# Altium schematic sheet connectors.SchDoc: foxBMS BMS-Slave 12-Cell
size A3; DocumentNumber: 10; SheetNumber: 10; SheetTotal: 15; AUTHOR: Fraunhofer IISB foxBMS Team; SheetDescription: Connectors
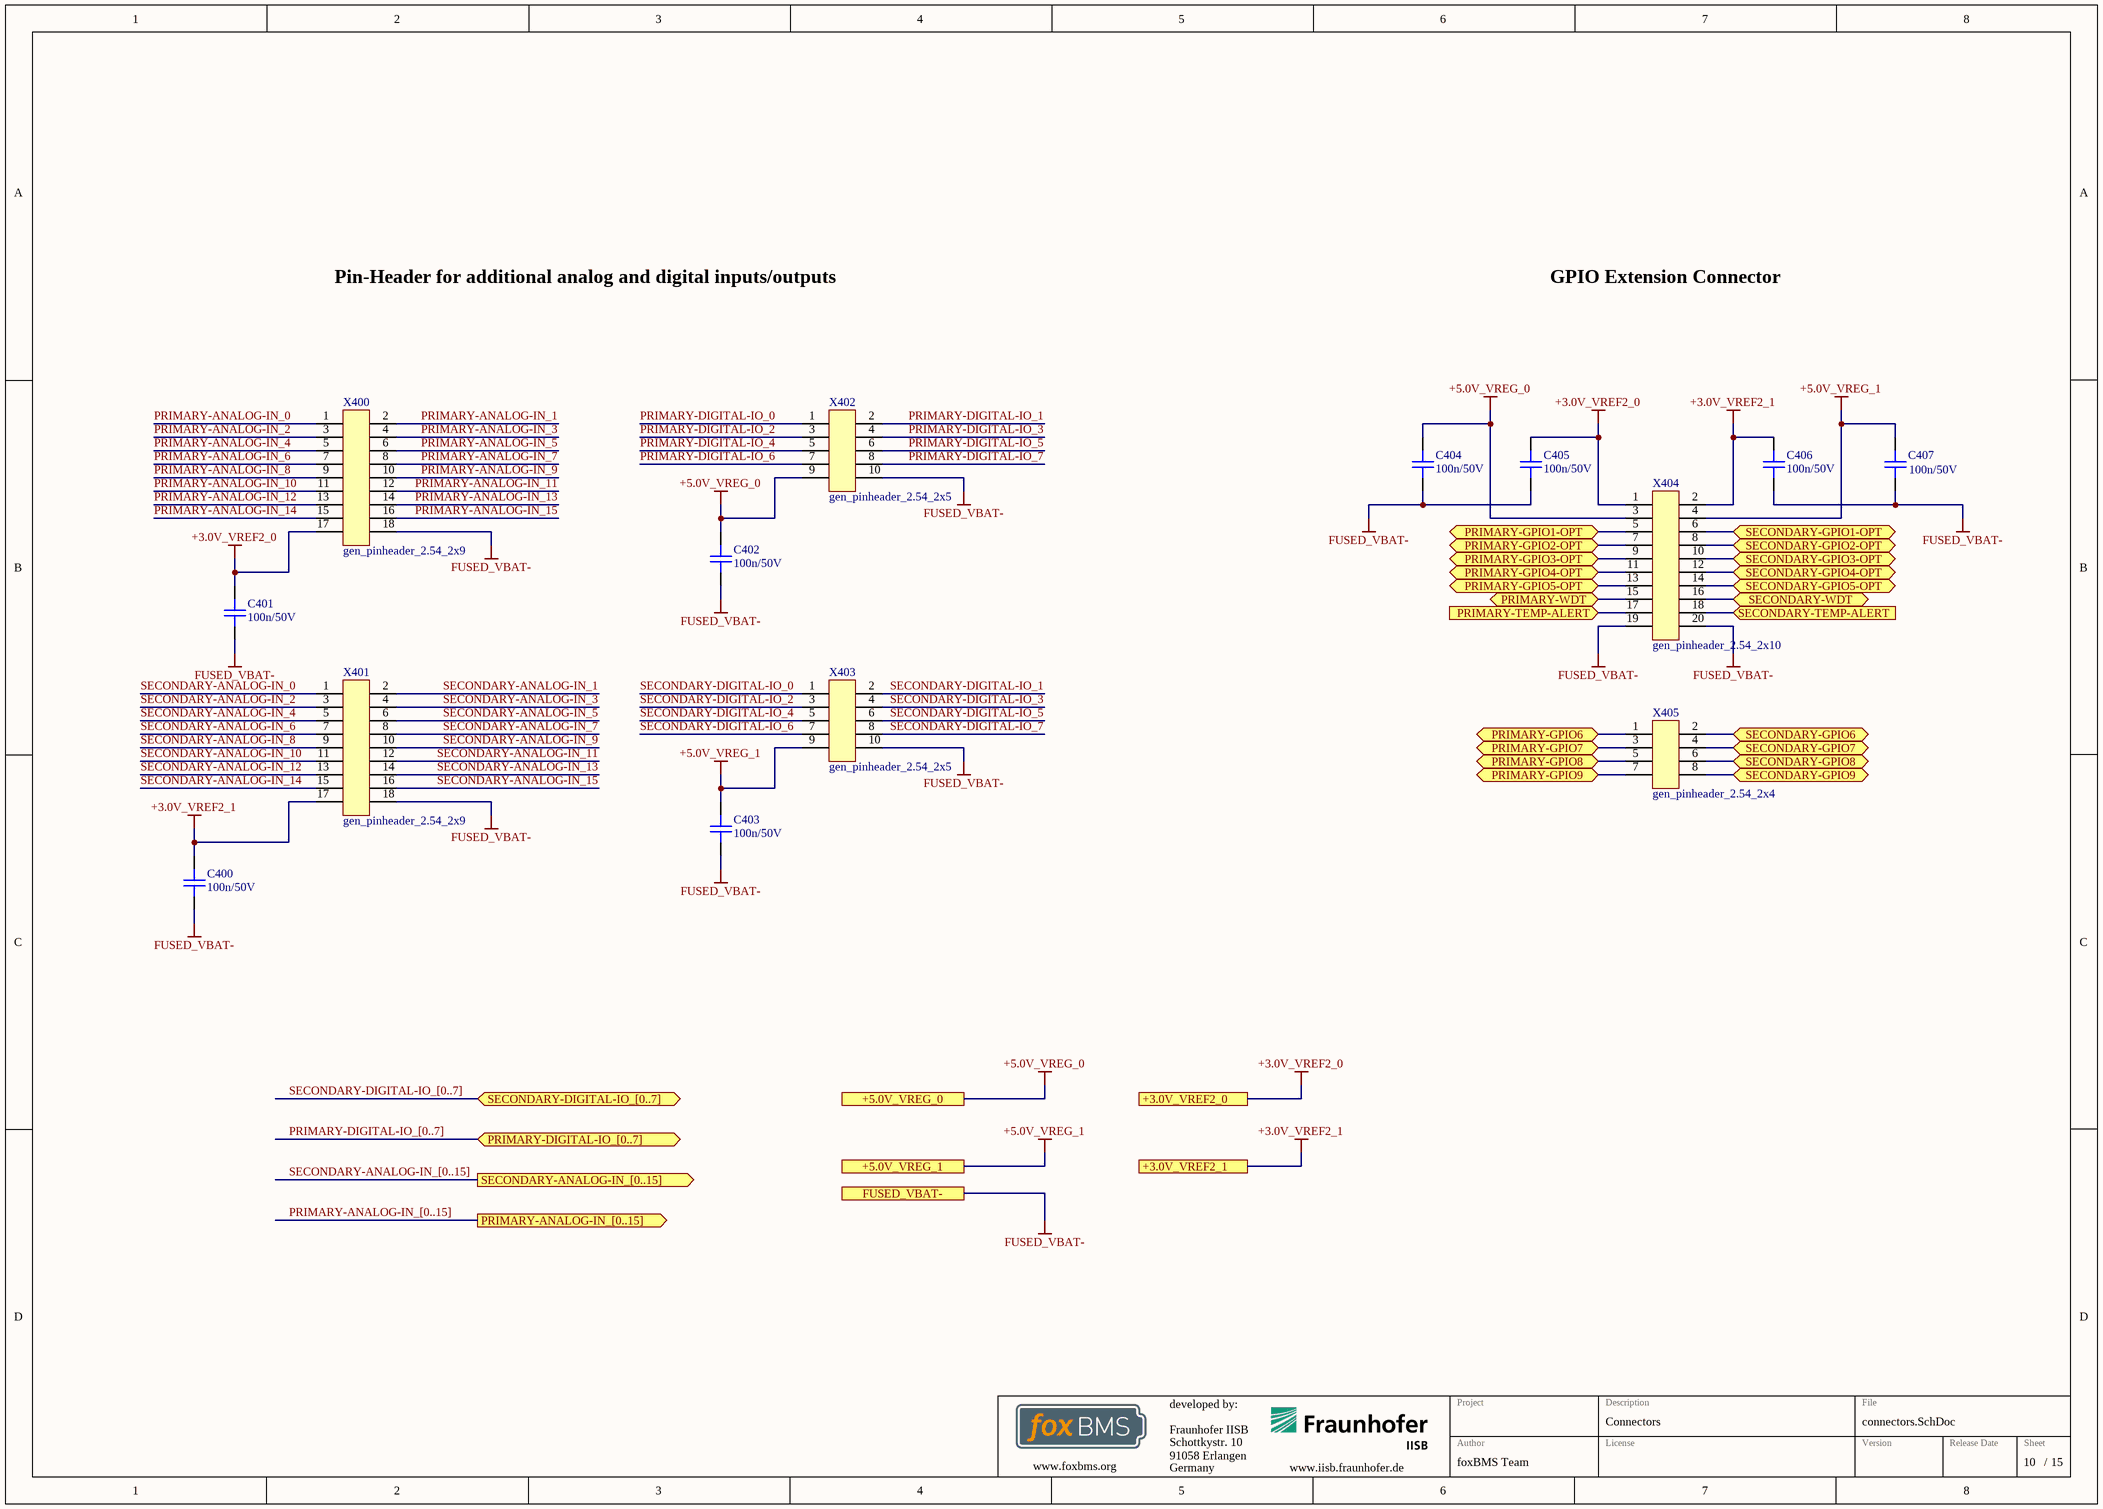
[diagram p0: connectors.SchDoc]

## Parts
C400  100n/50V  [CAPC1608X08N]
C401  100n/50V  [CAPC1608X08N]
C402  100n/50V  [CAPC1608X08N]
C403  100n/50V  [CAPC1608X08N]
C404  100n/50V  [CAPC1608X08N]
C405  100n/50V  [CAPC1608X08N]
C406  100n/50V  [CAPC1608X08N]
C407  100n/50V  [CAPC1608X08N]
X400  gen_pinheader_2.54_2x9  [Pinheader_2.54_2x9]
X401  gen_pinheader_2.54_2x9  [Pinheader_2.54_2x9]
X402  gen_pinheader_2.54_2x5  [Pinheader_2.54_2x5]
X403  gen_pinheader_2.54_2x5  [Pinheader_2.54_2x5]
X404  gen_pinheader_2.54_2x10  [Pinheader_2.54_2x10]
X405  gen_pinheader_2.54_2x4  [Pinheader_2.54_2x4]

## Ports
+3.0V_VREF2_0, +3.0V_VREF2_1, +5.0V_VREG_0, +5.0V_VREG_1, FUSED_VBAT-, PRIMARY-ANALOG-IN_[0..15] (out), PRIMARY-DIGITAL-IO_[0..7] (bidir), PRIMARY-GPIO1-OPT (bidir), PRIMARY-GPIO2-OPT (bidir), PRIMARY-GPIO3-OPT (bidir), PRIMARY-GPIO4-OPT (bidir), PRIMARY-GPIO5-OPT (bidir), PRIMARY-GPIO6 (bidir), PRIMARY-GPIO7 (bidir), PRIMARY-GPIO8 (bidir), PRIMARY-GPIO9 (bidir), PRIMARY-TEMP-ALERT (in), PRIMARY-WDT (bidir), SECONDARY-ANALOG-IN_[0..15] (out), SECONDARY-DIGITAL-IO_[0..7] (bidir), SECONDARY-GPIO1-OPT (bidir), SECONDARY-GPIO2-OPT (bidir), SECONDARY-GPIO3-OPT (bidir), SECONDARY-GPIO4-OPT (bidir), SECONDARY-GPIO5-OPT (bidir), SECONDARY-GPIO6 (bidir), SECONDARY-GPIO7 (bidir), SECONDARY-GPIO8 (bidir), SECONDARY-GPIO9 (bidir), SECONDARY-TEMP-ALERT (in), SECONDARY-WDT (bidir)

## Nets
+3.0V_VREF2_0: C401.2 C405.2 X400.17 X404.1 ; port +3.0V_VREF2_0
+3.0V_VREF2_1: C400.2 C406.2 X401.17 X404.2 ; port +3.0V_VREF2_1
+5.0V_VREG_0: C402.2 C404.2 X402.9 X404.3 ; port +5.0V_VREG_0
+5.0V_VREG_1: C403.2 C407.2 X403.9 X404.4 ; port +5.0V_VREG_1
FUSED_VBAT-: C400.1 C401.1 C402.1 C403.1 C404.1 C405.1 C406.1 C407.1 X400.18 X401.18 X402.10 X403.10 X404.19 X404.20 ; port FUSED_VBAT-
PRIMARY-ANALOG-IN_0: X400.1
PRIMARY-ANALOG-IN_1: X400.2
PRIMARY-ANALOG-IN_2: X400.3
PRIMARY-ANALOG-IN_3: X400.4
PRIMARY-ANALOG-IN_4: X400.5
PRIMARY-ANALOG-IN_5: X400.6
PRIMARY-ANALOG-IN_6: X400.7
PRIMARY-ANALOG-IN_7: X400.8
PRIMARY-ANALOG-IN_8: X400.9
PRIMARY-ANALOG-IN_9: X400.10
PRIMARY-ANALOG-IN_10: X400.11
PRIMARY-ANALOG-IN_11: X400.12
PRIMARY-ANALOG-IN_12: X400.13
PRIMARY-ANALOG-IN_13: X400.14
PRIMARY-ANALOG-IN_14: X400.15
PRIMARY-ANALOG-IN_15: X400.16
PRIMARY-DIGITAL-IO_0: X402.1
PRIMARY-DIGITAL-IO_1: X402.2
PRIMARY-DIGITAL-IO_2: X402.3
PRIMARY-DIGITAL-IO_3: X402.4
PRIMARY-DIGITAL-IO_4: X402.5
PRIMARY-DIGITAL-IO_5: X402.6
PRIMARY-DIGITAL-IO_6: X402.7
PRIMARY-DIGITAL-IO_7: X402.8
PRIMARY-GPIO1-OPT: X404.5 ; port PRIMARY-GPIO1-OPT
PRIMARY-GPIO2-OPT: X404.7 ; port PRIMARY-GPIO2-OPT
PRIMARY-GPIO3-OPT: X404.9 ; port PRIMARY-GPIO3-OPT
PRIMARY-GPIO4-OPT: X404.11 ; port PRIMARY-GPIO4-OPT
PRIMARY-GPIO5-OPT: X404.13 ; port PRIMARY-GPIO5-OPT
PRIMARY-GPIO6: X405.1 ; port PRIMARY-GPIO6
PRIMARY-GPIO7: X405.3 ; port PRIMARY-GPIO7
PRIMARY-GPIO8: X405.5 ; port PRIMARY-GPIO8
PRIMARY-GPIO9: X405.7 ; port PRIMARY-GPIO9
PRIMARY-TEMP-ALERT: X404.17 ; port PRIMARY-TEMP-ALERT
PRIMARY-WDT: X404.15 ; port PRIMARY-WDT
SECONDARY-ANALOG-IN_0: X401.1
SECONDARY-ANALOG-IN_1: X401.2
SECONDARY-ANALOG-IN_2: X401.3
SECONDARY-ANALOG-IN_3: X401.4
SECONDARY-ANALOG-IN_4: X401.5
SECONDARY-ANALOG-IN_5: X401.6
SECONDARY-ANALOG-IN_6: X401.7
SECONDARY-ANALOG-IN_7: X401.8
SECONDARY-ANALOG-IN_8: X401.9
SECONDARY-ANALOG-IN_9: X401.10
SECONDARY-ANALOG-IN_10: X401.11
SECONDARY-ANALOG-IN_11: X401.12
SECONDARY-ANALOG-IN_12: X401.13
SECONDARY-ANALOG-IN_13: X401.14
SECONDARY-ANALOG-IN_14: X401.15
SECONDARY-ANALOG-IN_15: X401.16
SECONDARY-DIGITAL-IO_0: X403.1
SECONDARY-DIGITAL-IO_1: X403.2
SECONDARY-DIGITAL-IO_2: X403.3
SECONDARY-DIGITAL-IO_3: X403.4
SECONDARY-DIGITAL-IO_4: X403.5
SECONDARY-DIGITAL-IO_5: X403.6
SECONDARY-DIGITAL-IO_6: X403.7
SECONDARY-DIGITAL-IO_7: X403.8
SECONDARY-GPIO1-OPT: X404.6 ; port SECONDARY-GPIO1-OPT
SECONDARY-GPIO2-OPT: X404.8 ; port SECONDARY-GPIO2-OPT
SECONDARY-GPIO3-OPT: X404.10 ; port SECONDARY-GPIO3-OPT
SECONDARY-GPIO4-OPT: X404.12 ; port SECONDARY-GPIO4-OPT
SECONDARY-GPIO5-OPT: X404.14 ; port SECONDARY-GPIO5-OPT
SECONDARY-GPIO6: X405.2 ; port SECONDARY-GPIO6
SECONDARY-GPIO7: X405.4 ; port SECONDARY-GPIO7
SECONDARY-GPIO8: X405.6 ; port SECONDARY-GPIO8
SECONDARY-GPIO9: X405.8 ; port SECONDARY-GPIO9
SECONDARY-TEMP-ALERT: X404.18 ; port SECONDARY-TEMP-ALERT
SECONDARY-WDT: X404.16 ; port SECONDARY-WDT

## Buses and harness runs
bus PRIMARY-ANALOG-IN_[0..15] = port PRIMARY-ANALOG-IN_[0..15]
bus PRIMARY-DIGITAL-IO_[0..7] = port PRIMARY-DIGITAL-IO_[0..7]
bus SECONDARY-ANALOG-IN_[0..15] = port SECONDARY-ANALOG-IN_[0..15]
bus SECONDARY-DIGITAL-IO_[0..7] = port SECONDARY-DIGITAL-IO_[0..7]

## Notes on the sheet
- Pin-Header for additional analog and digital inputs/outputs
- GPIO Extension Connector

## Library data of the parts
C400-C407 = gen_C_ceramic_100n_50V_X7R_0603: MLCC; Capacitance: 100n; Rated Voltage: 50V; Dielectric: X7R; Case EIA: 0603; Case Metric: 1608; PnP Package: C_0603_10; PnP Value: 100n/50V/X7R; PnP equipped: x; Automotive Qualified: True
X400 X401 = gen_pinheader_2.54_2x9: Standard Pinheader, THD, gerade, 2.54mm, 2-reihig; Circuits: 18; Rated Voltage: 250V; Rated Current: 3A; Automotive Qualified: False
X402 X403 = gen_pinheader_2.54_2x5: Standard Pinheader, THD, gerade, 2.54mm, 2-reihig; Circuits: 10; Rated Voltage: 250V; Rated Current: 3A; Automotive Qualified: False
X404 = gen_pinheader_2.54_2x10: Standard Pinheader, THD, gerade, 2.54mm, 2-reihig; Circuits: 20; Rated Voltage: 250V; Rated Current: 3A; Automotive Qualified: False
X405 = gen_pinheader_2.54_2x4: Standard Pinheader, THD, gerade, 2.54mm, 2-reihig; Circuits: 8; Rated Voltage: 250V; Rated Current: 3A; Automotive Qualified: False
